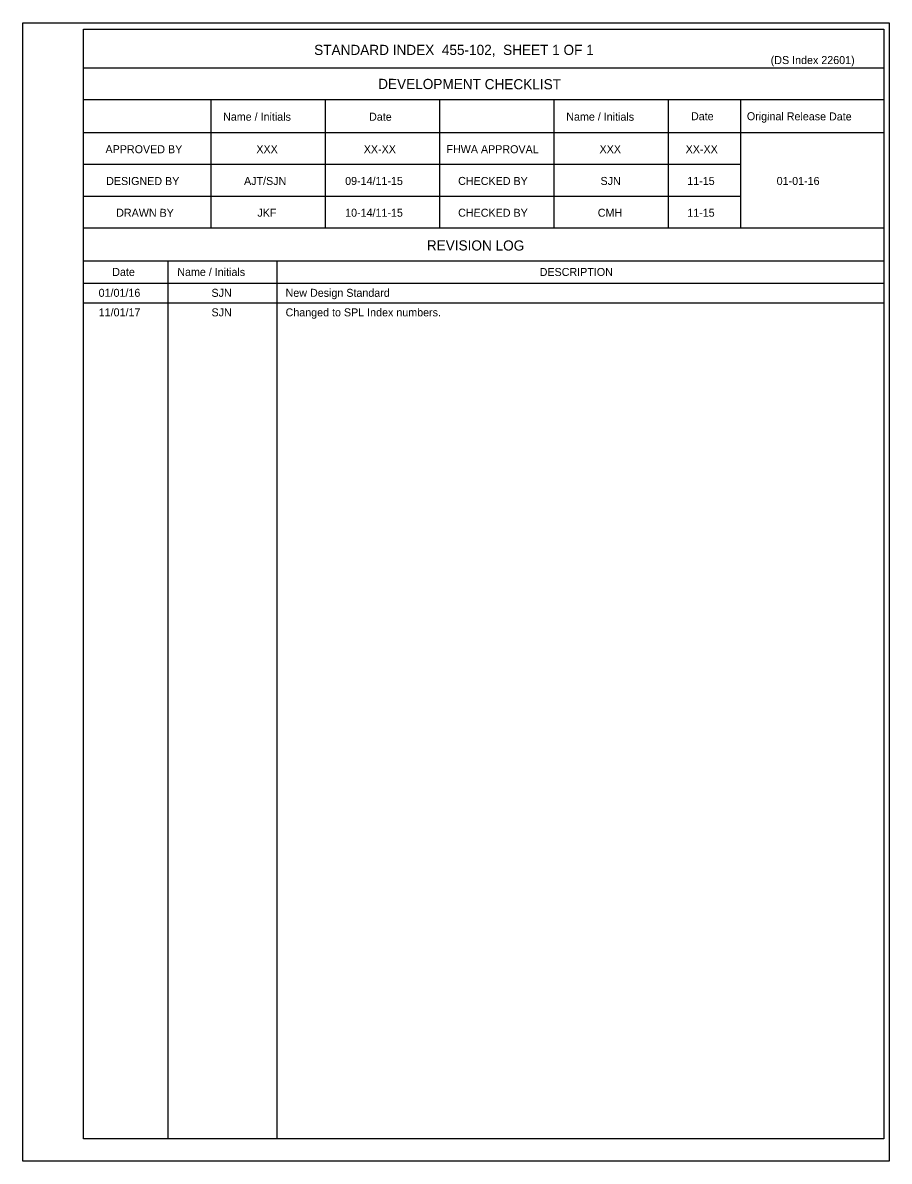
# Model space of a CAD drawing. Extents: x 112304.5 to 112376, y 111876.2 to 111935.5.
# Drawn here: x 112354.18 to 112376, y 111902.07 to 111930.74 of the extents above; entities that cross this region are included whole.
import ezdxf

# ---------------------------------------------------------------- set-up
doc = ezdxf.new("R2010")
doc.units = 0
for name, color, linetype in [('Border', 7, 'Continuous'), ('PlotBorder_dp', 7, 'Continuous'), ('SheetBorder_dp', 7, 'Continuous')]:
    doc.layers.add(name, color=color, linetype=linetype)

msp = doc.modelspace()

# ---------------------------------------------------------------- linework, layer by layer
at = {"layer": 'Border'}
for p, q in [((112375.861, 111929.595), (112355.714, 111929.595)), ((112375.861, 111928.795), (112355.714, 111928.795)), ((112358.914, 111928.795), (112358.914, 111925.567)), ((112361.794, 111928.795), (112361.794, 111925.567)), ((112364.674, 111928.795), (112364.674, 111925.567)), ((112367.554, 111928.795), (112367.554, 111925.567)), ((112370.434, 111928.795), (112370.434, 111925.567)), ((112372.249, 111928.795), (112372.249, 111925.567)), ((112375.861, 111927.967), (112355.714, 111927.967)), ((112372.249, 111927.167), (112355.714, 111927.167)), ((112372.249, 111926.367), (112355.714, 111926.367)), ((112375.861, 111925.567), (112355.714, 111925.567)), ((112375.861, 111924.739), (112355.714, 111924.739)), ((112357.834, 111924.739), (112357.834, 111902.633)), ((112360.576, 111924.739), (112360.576, 111902.633)), ((112375.861, 111924.175), (112355.714, 111924.175)), ((112355.714, 111923.683), (112375.86, 111923.683))]:
    msp.add_line(p, q, dxfattribs=at)
msp.add_lwpolyline([(112355.714, 111930.575), (112375.861, 111930.575), (112375.861, 111902.633), (112355.714, 111902.633)], close=True, dxfattribs=at)
at = {"layer": 'PlotBorder_dp'}
msp.add_line((112354.183, 111902.071), (112354.183, 111902.071), dxfattribs=at)
msp.add_lwpolyline([(112354.183, 111930.738), (112375.997, 111930.738), (112375.997, 111902.071), (112354.183, 111902.071)], close=True, dxfattribs=at)

# ---------------------------------------------------------------- texts
at = {"layer": 'SheetBorder_dp'}
for s, height, p in [('STANDARD INDEX  455-102,  SHEET 1 OF 1', 0.256, (112361.519, 111929.927)), ('(DS Index 22601)', 0.2016, (112373.013, 111929.698)), ('XXX', 0.2016, (112360.064, 111927.454)), ('XX-XX', 0.2016, (112362.768, 111927.454)), ('XXX', 0.2016, (112368.704, 111927.454)), ('XX-XX', 0.2016, (112370.872, 111927.454)), ('AJT/SJN', 0.2016, (112359.754, 111926.654)), ('09-14/11-15', 0.2016, (112362.299, 111926.654)), ('SJN', 0.2016, (112368.728, 111926.654)), ('11-15', 0.2016, (112370.912, 111926.654)), ('01-01-16', 0.2016, (112373.163, 111926.654)), ('JKF', 0.2016, (112360.09, 111925.854)), ('10-14/11-15', 0.2016, (112362.299, 111925.854)), ('CMH', 0.2016, (112368.659, 111925.854)), ('11-15', 0.2016, (112370.912, 111925.854)), ('DESCRIPTION', 0.2016, (112367.197, 111924.362)), ('01/01/16', 0.2016, (112356.093, 111923.837)), ('SJN', 0.2016, (112358.935, 111923.837)), ('New Design Standard', 0.2016, (112360.8, 111923.837)), ('11/01/17', 0.2016, (112356.095, 111923.345)), ('SJN', 0.2016, (112358.935, 111923.345)), ('Changed to SPL Index numbers.', 0.2016, (112360.8, 111923.345))]:
    msp.add_text(s, height=height, dxfattribs=at).set_placement(p)
for s, height, p in [('DEVELOPMENT CHECKLIST', 0.256, (112363.13, 111929.071)), ('Original Release Date', 0.2016, (112372.413, 111928.284)), ('Name / Initials', 0.2016, (112359.226, 111928.274)), ('Date', 0.2016, (112362.901, 111928.272)), ('Name / Initials', 0.2016, (112367.866, 111928.274)), ('Date', 0.2016, (112371.006, 111928.284)), ('APPROVED BY', 0.2016, (112356.266, 111927.455)), ('FHWA APPROVAL', 0.2016, (112364.849, 111927.456)), ('DESIGNED BY', 0.2016, (112356.282, 111926.654)), ('CHECKED BY', 0.2016, (112365.144, 111926.655)), ('DRAWN BY', 0.2016, (112356.535, 111925.854)), ('CHECKED BY', 0.2016, (112365.144, 111925.855)), ('REVISION LOG', 0.256, (112364.355, 111925.006)), ('Date', 0.2016, (112356.436, 111924.363)), ('Name / Initials', 0.2016, (112358.073, 111924.364))]:
    msp.add_text(s, height=height, rotation=359.8756, dxfattribs=at).set_placement(p)

doc.saveas('drawing.dxf')
